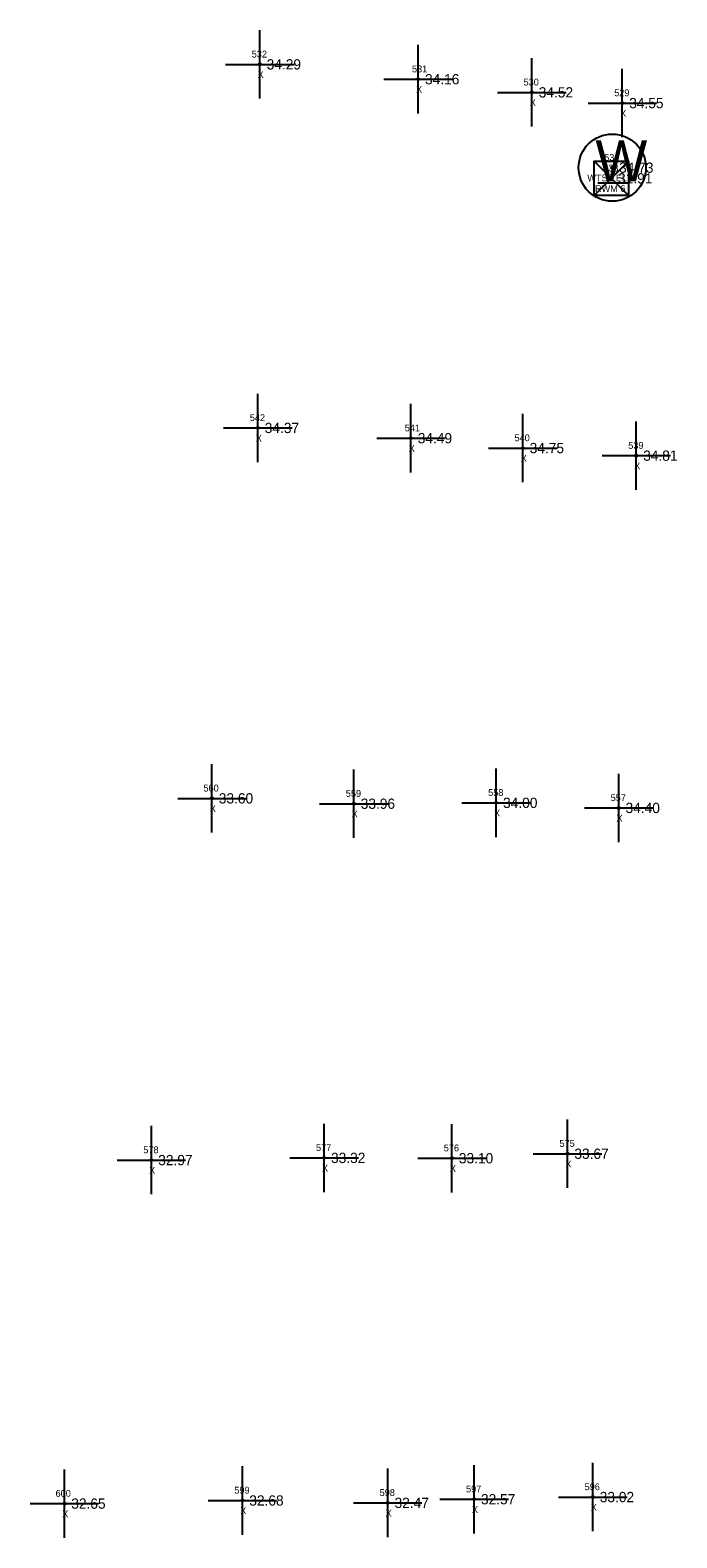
# Model space of a CAD drawing. Extents: x 2042211 to 2045853, y 303080 to 309569.
# Drawn here: x 2042712.7 to 2042807.2, y 307322.8 to 307543.1 of the extents above; entities that cross this region are included whole.
import ezdxf

# ---------------------------------------------------------------- set-up
doc = ezdxf.new("R2010")
doc.units = 0
for name, color, linetype in [('BR_500YR_SCOUR', 7, 'Continuous'), ('RD_EX_Misc', 7, 'Continuous'), ('RD_EX_Misc_txCode', 7, 'Continuous'), ('RD_EX_RW_TxCode', 7, 'Continuous'), ('RD_EX_TX_Misc_ELEV', 7, 'Continuous'), ('RD_EX_TX_RW_ELEV', 7, 'Continuous'), ('RD_EX_TX_UT_ELEV', 7, 'Continuous'), ('RD_EX_UT_txCode', 7, 'Continuous'), ('RD_SMD_Locator', 7, 'Continuous')]:
    doc.layers.add(name, color=color, linetype=linetype)

msp = doc.modelspace()

# ---------------------------------------------------------------- linework, layer by layer
at = {"layer": 'BR_500YR_SCOUR'}
for p, q in [((2042795.1, 307518.91), (2042800.1, 307523.91)), ((2042800.1, 307518.91), (2042795.1, 307523.91)), ((2042800.1, 307523.91), (2042800.1, 307518.91)), ((2042795.62, 307520.76), (2042800.25, 307520.76))]:
    msp.add_line(p, q, dxfattribs=at)
msp.add_lwpolyline([(2042795.1, 307518.91), (2042795.1, 307523.91), (2042800.1, 307523.91), (2042800.1, 307518.91)], close=True, dxfattribs=at)
for centre, radius in [((2042797.75, 307522.97), 4.91), ((2042797.6, 307521.41), 0.15), ((2042797.75, 307522.97), 0.15)]:
    msp.add_circle(centre, radius, dxfattribs=at)
at = {"layer": 'RD_EX_Misc'}
for p, q in [((2042746.27, 307533.06), (2042746.27, 307543.06)), ((2042769.4, 307530.89), (2042769.4, 307540.89)), ((2042786.01, 307528.97), (2042786.01, 307538.97)), ((2042741.27, 307538.06), (2042751.27, 307538.06)), ((2042799.22, 307527.4), (2042799.22, 307537.4)), ((2042764.4, 307535.89), (2042774.4, 307535.89)), ((2042781.01, 307533.97), (2042791.01, 307533.97)), ((2042794.22, 307532.4), (2042804.22, 307532.4)), ((2042745.99, 307479.95), (2042745.99, 307489.95)), ((2042768.34, 307478.45), (2042768.34, 307488.45)), ((2042784.69, 307477.01), (2042784.69, 307487.01)), ((2042740.99, 307484.95), (2042750.99, 307484.95)), ((2042801.26, 307475.9), (2042801.26, 307485.9)), ((2042763.34, 307483.45), (2042773.34, 307483.45)), ((2042779.69, 307482.01), (2042789.69, 307482.01)), ((2042796.26, 307480.9), (2042806.26, 307480.9)), ((2042739.28, 307425.84), (2042739.28, 307435.84)), ((2042760.01, 307425.06), (2042760.01, 307435.06)), ((2042780.8, 307425.19), (2042780.8, 307435.19)), ((2042798.69, 307424.44), (2042798.69, 307434.44)), ((2042734.28, 307430.84), (2042744.28, 307430.84)), ((2042755.01, 307430.06), (2042765.01, 307430.06)), ((2042775.8, 307430.19), (2042785.8, 307430.19)), ((2042793.69, 307429.44), (2042803.69, 307429.44)), ((2042730.43, 307373), (2042730.43, 307383)), ((2042755.67, 307373.32), (2042755.67, 307383.32)), ((2042774.34, 307373.27), (2042774.34, 307383.27)), ((2042791.21, 307373.93), (2042791.21, 307383.93)), ((2042750.67, 307378.32), (2042760.67, 307378.32)), ((2042769.34, 307378.27), (2042779.34, 307378.27)), ((2042786.21, 307378.93), (2042796.21, 307378.93)), ((2042725.43, 307378), (2042735.43, 307378)), ((2042717.73, 307322.82), (2042717.73, 307332.82)), ((2042743.73, 307323.28), (2042743.73, 307333.28)), ((2042764.95, 307322.93), (2042764.95, 307332.93)), ((2042777.57, 307323.46), (2042777.57, 307333.46)), ((2042794.92, 307323.78), (2042794.92, 307333.78)), ((2042712.73, 307327.82), (2042722.73, 307327.82)), ((2042738.73, 307328.28), (2042748.73, 307328.28)), ((2042759.95, 307327.93), (2042769.95, 307327.93)), ((2042772.57, 307328.46), (2042782.57, 307328.46)), ((2042789.92, 307328.78), (2042799.92, 307328.78))]:
    msp.add_line(p, q, dxfattribs=at)
at = {"layer": 'RD_SMD_Locator'}
for centre in [(2042746.27, 307538.06), (2042769.4, 307535.89), (2042786.01, 307533.97), (2042799.22, 307532.4), (2042745.99, 307484.95), (2042768.34, 307483.45), (2042784.69, 307482.01), (2042801.26, 307480.9), (2042739.28, 307430.84), (2042760.01, 307430.06), (2042780.8, 307430.19), (2042798.69, 307429.44), (2042730.43, 307378), (2042755.67, 307378.32), (2042774.34, 307378.27), (2042791.21, 307378.93), (2042717.73, 307327.82), (2042743.73, 307328.28), (2042764.95, 307327.93), (2042777.57, 307328.46), (2042794.92, 307328.78)]:
    msp.add_circle(centre, 0.15, dxfattribs=at)

# ---------------------------------------------------------------- texts
at = {"layer": 'BR_500YR_SCOUR'}
msp.add_text('W', height=6, dxfattribs=at).set_placement((2042795.29, 307520.97))
at = {"layer": 'RD_EX_Misc_txCode'}
for s, p in [('532', (2042745.09, 307539.06)), ('X', (2042745.95, 307536.06)), ('531', (2042768.5, 307536.89)), ('X', (2042769.09, 307533.89)), ('530', (2042784.79, 307534.97)), ('529', (2042798.03, 307533.4)), ('X', (2042785.7, 307531.97)), ('X', (2042798.9, 307530.4)), ('542', (2042744.81, 307485.95)), ('X', (2042745.68, 307482.95)), ('541', (2042767.44, 307484.45)), ('540', (2042783.47, 307483.01)), ('X', (2042768.02, 307481.45)), ('539', (2042800.08, 307481.9)), ('X', (2042784.38, 307480.01)), ('X', (2042800.95, 307478.9)), ('560', (2042738.04, 307431.84)), ('559', (2042758.83, 307431.06)), ('558', (2042779.62, 307431.19)), ('557', (2042797.51, 307430.44)), ('X', (2042738.97, 307428.84)), ('X', (2042759.69, 307428.06)), ('X', (2042780.49, 307428.19)), ('X', (2042798.37, 307427.44)), ('577', (2042754.48, 307379.32)), ('576', (2042773.14, 307379.27)), ('575', (2042790.03, 307379.93)), ('578', (2042729.25, 307379)), ('X', (2042730.11, 307376)), ('X', (2042755.35, 307376.32)), ('X', (2042774.03, 307376.27)), ('X', (2042790.9, 307376.93)), ('600', (2042716.44, 307328.82)), ('599', (2042742.55, 307329.28)), ('598', (2042763.77, 307328.93)), ('597', (2042776.39, 307329.46)), ('596', (2042793.71, 307329.78)), ('X', (2042777.25, 307326.46)), ('X', (2042794.6, 307326.78)), ('X', (2042717.41, 307325.82)), ('X', (2042743.41, 307326.28)), ('X', (2042764.64, 307325.93))]:
    msp.add_text(s, height=1, dxfattribs=at).set_placement(p)
at = {"layer": 'RD_EX_RW_TxCode'}
for s, p in [('533', (2042796.42, 307522.41)), ('RWM 6', (2042795.22, 307519.41))]:
    msp.add_text(s, height=1, dxfattribs=at).set_placement(p)
at = {"layer": 'RD_EX_TX_Misc_ELEV'}
for s, p in [('34.29', (2042747.27, 307537.31)), ('34.16', (2042770.4, 307535.14)), ('34.52', (2042787.01, 307533.22)), ('34.55', (2042800.22, 307531.65)), ('34.37', (2042746.99, 307484.2)), ('34.49', (2042769.34, 307482.7)), ('34.75', (2042785.69, 307481.26)), ('34.81', (2042802.26, 307480.15)), ('33.60', (2042740.28, 307430.09)), ('34.00', (2042781.8, 307429.44)), ('33.96', (2042761.01, 307429.31)), ('34.40', (2042799.69, 307428.69)), ('32.97', (2042731.43, 307377.25)), ('33.32', (2042756.67, 307377.57)), ('33.10', (2042775.34, 307377.52)), ('33.67', (2042792.21, 307378.18)), ('32.65', (2042718.73, 307327.07)), ('32.68', (2042744.73, 307327.53)), ('32.47', (2042765.95, 307327.18)), ('32.57', (2042778.57, 307327.71)), ('33.02', (2042795.92, 307328.03))]:
    msp.add_text(s, height=1.5, dxfattribs=at).set_placement(p)
at = {"layer": 'RD_EX_TX_RW_ELEV'}
msp.add_text('31.91', height=1.5, dxfattribs=at).set_placement((2042798.6, 307520.66))
at = {"layer": 'RD_EX_TX_UT_ELEV'}
msp.add_text('34.73', height=1.5, dxfattribs=at).set_placement((2042798.75, 307522.22))
at = {"layer": 'RD_EX_UT_txCode'}
for s, p in [('534', (2042796.57, 307523.97)), ('WTS TELE', (2042794.1, 307520.97))]:
    msp.add_text(s, height=1, dxfattribs=at).set_placement(p)

doc.saveas('drawing.dxf')
